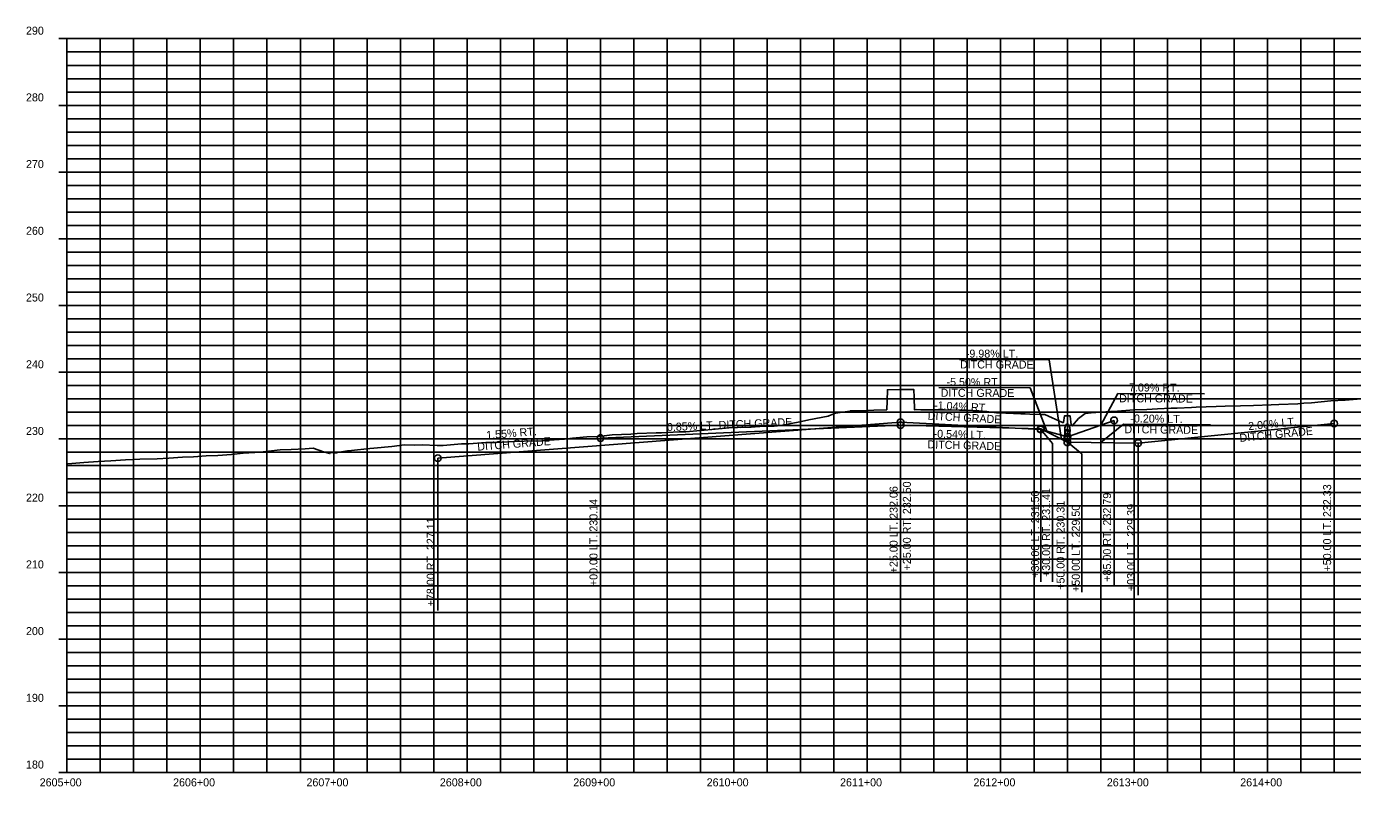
# Model space of a CAD drawing. Extents: x 921603 to 924670, y 1759276 to 1766491.
# Drawn here: x 921610 to 922604, y 1765922 to 1766491 of the extents above; entities that cross this region are included whole.
import ezdxf

# ---------------------------------------------------------------- set-up
doc = ezdxf.new("R2010")
doc.units = 0
for name, color, linetype in [('63', 7, 'Continuous'), ('R_Axis_Annotation', 7, 'Continuous'), ('R_Exist Surface', 7, 'Continuous'), ('R_Grid', 7, 'Continuous'), ('R_Grid Annot', 7, 'Continuous'), ('R_Grid_Minor', 7, 'Continuous'), ('R_Vert Alg', 7, 'Continuous'), ('R_Vert Alg Annot', 7, 'Continuous')]:
    doc.layers.add(name, color=color, linetype=linetype)

msp = doc.modelspace()

# ---------------------------------------------------------------- linework, layer by layer
at = {"layer": 'R_Exist Surface'}
msp.add_lwpolyline([(921639.83, 1766163.54), (921640.46, 1766163.58), (921652.44, 1766164.55), (921663.23, 1766165.41), (921672.8, 1766165.99), (921683.86, 1766166.64), (921694.6, 1766167.01), (921707.48, 1766167.45), (921716.34, 1766167.97), (921726.4, 1766168.63), (921734.64, 1766168.93), (921744.34, 1766169.54), (921752.93, 1766169.86), (921763.3, 1766170.65), (921772.04, 1766171.57), (921784.88, 1766172.47), (921791.06, 1766173.12), (921799.81, 1766174.16), (921807.84, 1766174.43), (921818.48, 1766174.79), (921824.45, 1766175.29), (921832.27, 1766172.66), (921836.95, 1766171.33), (921837.04, 1766171.46), (921837.81, 1766172.06), (921840.02, 1766171.81), (921842, 1766171.78), (921842.41, 1766171.85), (921842.78, 1766172.09), (921844.22, 1766172.46), (921850.22, 1766173.33), (921853.25, 1766173.68), (921866.84, 1766174.99), (921870.05, 1766175.35), (921883.47, 1766176.65), (921892.95, 1766177.74), (921900.25, 1766177.52), (921906.25, 1766177.98), (921917.38, 1766177.39), (921921.94, 1766177.46), (921935.54, 1766178.57), (921941.18, 1766178.61), (921953.79, 1766179.61), (921961.61, 1766179.71), (921974.8, 1766180.33), (921982.51, 1766180.7), (921995.91, 1766180.74), (922001.2, 1766181.24), (922012.78, 1766182.23), (922018.74, 1766182.81), (922029.67, 1766183.75), (922038.61, 1766184.15), (922048.55, 1766185.45), (922062.53, 1766185.79), (922067.36, 1766186.3), (922081.47, 1766186.87), (922085.62, 1766186.95), (922098.93, 1766187.48), (922103.88, 1766187.56), (922117.48, 1766188.9), (922123.23, 1766189.24), (922135.99, 1766190.49), (922142.59, 1766190.84), (922152.91, 1766191.11), (922158.79, 1766191.65), (922170.16, 1766191.92), (922174.93, 1766192.33), (922189.32, 1766195.13), (922192.7, 1766195.82), (922195.92, 1766196.48), (922210.63, 1766199.33), (922211.01, 1766199.6), (922215.97, 1766201.57), (922226.71, 1766203.19), (922227.06, 1766203.22), (922227.24, 1766203.23), (922240.42, 1766203.57), (922244.84, 1766203.81), (922254.29, 1766204.12), (922254.31, 1766204.13), (922254.5, 1766204.14), (922254.7, 1766210.95), (922254.99, 1766219.19), (922264.01, 1766219.38), (922274.66, 1766219.43), (922274.88, 1766213.34), (922275.19, 1766204.21), (922277.01, 1766204.3), (922280.01, 1766204.21), (922290.9, 1766204), (922297.23, 1766204.03), (922309.02, 1766203.78), (922314.46, 1766203.8), (922323.57, 1766203.34), (922329.25, 1766202.74), (922336.63, 1766201.96), (922343.66, 1766201.51), (922354.86, 1766201.08), (922358.11, 1766201), (922361.8, 1766200.91), (922370.52, 1766200.48), (922372.38, 1766200.54), (922372.95, 1766200.55), (922386.25, 1766194.5), (922387.02, 1766194.64), (922387.67, 1766199.57), (922389.92, 1766199.56), (922391.76, 1766199.47), (922392.05, 1766199.39), (922392.76, 1766192.74), (922393.45, 1766192.07), (922398.1, 1766197.47), (922403.12, 1766201.24), (922407.74, 1766201.84), (922422.2, 1766202.74), (922424.5, 1766202.83), (922439.72, 1766204.09), (922449.5, 1766204.24), (922457.48, 1766204.74), (922467.57, 1766205.25), (922472.03, 1766205.36), (922482.89, 1766205.92), (922486.51, 1766206.01), (922501.27, 1766206.62), (922508.12, 1766206.75), (922519.58, 1766206.97), (922529.44, 1766207.31), (922542.67, 1766207.81), (922548.29, 1766208.2), (922562.6, 1766208.69), (922567.13, 1766209.04), (922572.98, 1766209.4), (922587.24, 1766210.75), (922597.98, 1766211.4), (922607.18, 1766212.19)], dxfattribs=at)
at = {"layer": 'R_Grid'}
for p, q in [((921639.83, 1765932.26), (921639.83, 1766482.26)), ((921639.83, 1766482.26), (923139.83, 1766482.26)), ((921639.83, 1766482.26), (923139.83, 1766482.26)), ((921739.83, 1765932.26), (921739.83, 1766482.26)), ((921839.83, 1765932.26), (921839.83, 1766482.26)), ((921939.83, 1765932.26), (921939.83, 1766482.26)), ((922039.83, 1765932.26), (922039.83, 1766482.26)), ((922139.83, 1765932.26), (922139.83, 1766482.26)), ((922239.83, 1765932.26), (922239.83, 1766482.26)), ((922339.83, 1765932.26), (922339.83, 1766482.26)), ((922439.83, 1765932.26), (922439.83, 1766482.26)), ((922539.83, 1765932.26), (922539.83, 1766482.26)), ((921639.83, 1766432.26), (923139.83, 1766432.26)), ((921639.83, 1766382.26), (923139.83, 1766382.26)), ((921639.83, 1766332.26), (923139.83, 1766332.26)), ((921639.83, 1766282.26), (923139.83, 1766282.26)), ((921639.83, 1766232.26), (923139.83, 1766232.26)), ((921639.83, 1766182.26), (923139.83, 1766182.26)), ((921639.83, 1766132.26), (923139.83, 1766132.26)), ((921639.83, 1766082.26), (923139.83, 1766082.26)), ((921639.83, 1766032.26), (923139.83, 1766032.26)), ((921639.83, 1765982.26), (923139.83, 1765982.26)), ((921639.83, 1765932.26), (923139.83, 1765932.26))]:
    msp.add_line(p, q, dxfattribs=at)
at = {"layer": 'R_Grid Annot'}
for p, q in [((921633.83, 1766482.26), (921639.83, 1766482.26)), ((921633.83, 1766482.26), (921639.83, 1766482.26)), ((921639.83, 1766472.26), (921642.83, 1766472.26)), ((921639.83, 1766462.26), (921642.83, 1766462.26)), ((921639.83, 1766452.26), (921642.83, 1766452.26)), ((921639.83, 1766442.26), (921642.83, 1766442.26)), ((921633.83, 1766432.26), (921639.83, 1766432.26)), ((921639.83, 1766422.26), (921642.83, 1766422.26)), ((921639.83, 1766412.26), (921642.83, 1766412.26)), ((921639.83, 1766402.26), (921642.83, 1766402.26)), ((921639.83, 1766392.26), (921642.83, 1766392.26)), ((921633.83, 1766382.26), (921639.83, 1766382.26)), ((921639.83, 1766372.26), (921642.83, 1766372.26)), ((921639.83, 1766362.26), (921642.83, 1766362.26)), ((921639.83, 1766352.26), (921642.83, 1766352.26)), ((921639.83, 1766342.26), (921642.83, 1766342.26)), ((921633.83, 1766332.26), (921639.83, 1766332.26)), ((921639.83, 1766322.26), (921642.83, 1766322.26)), ((921639.83, 1766312.26), (921642.83, 1766312.26)), ((921639.83, 1766302.26), (921642.83, 1766302.26)), ((921639.83, 1766292.26), (921642.83, 1766292.26)), ((921633.83, 1766282.26), (921639.83, 1766282.26)), ((921639.83, 1766272.26), (921642.83, 1766272.26)), ((921639.83, 1766262.26), (921642.83, 1766262.26)), ((921639.83, 1766252.26), (921642.83, 1766252.26)), ((921639.83, 1766242.26), (921642.83, 1766242.26)), ((921633.83, 1766232.26), (921639.83, 1766232.26)), ((921639.83, 1766222.26), (921642.83, 1766222.26)), ((921639.83, 1766212.26), (921642.83, 1766212.26)), ((921639.83, 1766202.26), (921642.83, 1766202.26)), ((921639.83, 1766192.26), (921642.83, 1766192.26)), ((921633.83, 1766182.26), (921639.83, 1766182.26)), ((921639.83, 1766172.26), (921642.83, 1766172.26)), ((921639.83, 1766162.26), (921642.83, 1766162.26)), ((921639.83, 1766152.26), (921642.83, 1766152.26)), ((921639.83, 1766142.26), (921642.83, 1766142.26)), ((921633.83, 1766132.26), (921639.83, 1766132.26)), ((921639.83, 1766122.26), (921642.83, 1766122.26)), ((921639.83, 1766112.26), (921642.83, 1766112.26)), ((921639.83, 1766102.26), (921642.83, 1766102.26)), ((921639.83, 1766092.26), (921642.83, 1766092.26)), ((921633.83, 1766082.26), (921639.83, 1766082.26)), ((921639.83, 1766072.26), (921642.83, 1766072.26)), ((921639.83, 1766062.26), (921642.83, 1766062.26)), ((921639.83, 1766052.26), (921642.83, 1766052.26)), ((921639.83, 1766042.26), (921642.83, 1766042.26)), ((921633.83, 1766032.26), (921639.83, 1766032.26)), ((921639.83, 1766022.26), (921642.83, 1766022.26)), ((921639.83, 1766012.26), (921642.83, 1766012.26)), ((921639.83, 1766002.26), (921642.83, 1766002.26)), ((921639.83, 1765992.26), (921642.83, 1765992.26)), ((921633.83, 1765982.26), (921639.83, 1765982.26)), ((921639.83, 1765972.26), (921642.83, 1765972.26)), ((921639.83, 1765962.26), (921642.83, 1765962.26)), ((921639.83, 1765952.26), (921642.83, 1765952.26)), ((921639.83, 1765942.26), (921642.83, 1765942.26)), ((921633.83, 1765932.26), (921639.83, 1765932.26))]:
    msp.add_line(p, q, dxfattribs=at)
at = {"layer": 'R_Grid_Minor'}
for p, q in [((921664.83, 1765932.26), (921664.83, 1766482.26)), ((921689.83, 1765932.26), (921689.83, 1766482.26)), ((921714.83, 1765932.26), (921714.83, 1766482.26)), ((921764.83, 1765932.26), (921764.83, 1766482.26)), ((921789.83, 1765932.26), (921789.83, 1766482.26)), ((921814.83, 1765932.26), (921814.83, 1766482.26)), ((921864.83, 1765932.26), (921864.83, 1766482.26)), ((921889.83, 1765932.26), (921889.83, 1766482.26)), ((921914.83, 1765932.26), (921914.83, 1766482.26)), ((921964.83, 1765932.26), (921964.83, 1766482.26)), ((921989.83, 1765932.26), (921989.83, 1766482.26)), ((922014.83, 1765932.26), (922014.83, 1766482.26)), ((922064.83, 1765932.26), (922064.83, 1766482.26)), ((922089.83, 1765932.26), (922089.83, 1766482.26)), ((922114.83, 1765932.26), (922114.83, 1766482.26)), ((922164.83, 1765932.26), (922164.83, 1766482.26)), ((922189.83, 1765932.26), (922189.83, 1766482.26)), ((922214.83, 1765932.26), (922214.83, 1766482.26)), ((922264.83, 1765932.26), (922264.83, 1766482.26)), ((922289.83, 1765932.26), (922289.83, 1766482.26)), ((922314.83, 1765932.26), (922314.83, 1766482.26)), ((922364.83, 1765932.26), (922364.83, 1766482.26)), ((922389.83, 1765932.26), (922389.83, 1766482.26)), ((922414.83, 1765932.26), (922414.83, 1766482.26)), ((922464.83, 1765932.26), (922464.83, 1766482.26)), ((922489.83, 1765932.26), (922489.83, 1766482.26)), ((922514.83, 1765932.26), (922514.83, 1766482.26)), ((922564.83, 1765932.26), (922564.83, 1766482.26)), ((922589.83, 1765932.26), (922589.83, 1766482.26)), ((921639.83, 1766472.26), (923139.83, 1766472.26)), ((921639.83, 1766462.26), (923139.83, 1766462.26)), ((921639.83, 1766452.26), (923139.83, 1766452.26)), ((921639.83, 1766442.26), (923139.83, 1766442.26)), ((921639.83, 1766422.26), (923139.83, 1766422.26)), ((921639.83, 1766412.26), (923139.83, 1766412.26)), ((921639.83, 1766402.26), (923139.83, 1766402.26)), ((921639.83, 1766392.26), (923139.83, 1766392.26)), ((921639.83, 1766372.26), (923139.83, 1766372.26)), ((921639.83, 1766362.26), (923139.83, 1766362.26)), ((921639.83, 1766352.26), (923139.83, 1766352.26)), ((921639.83, 1766342.26), (923139.83, 1766342.26)), ((921639.83, 1766322.26), (923139.83, 1766322.26)), ((921639.83, 1766312.26), (923139.83, 1766312.26)), ((921639.83, 1766302.26), (923139.83, 1766302.26)), ((921639.83, 1766292.26), (923139.83, 1766292.26)), ((921639.83, 1766272.26), (923139.83, 1766272.26)), ((921639.83, 1766262.26), (923139.83, 1766262.26)), ((921639.83, 1766252.26), (923139.83, 1766252.26)), ((921639.83, 1766242.26), (923139.83, 1766242.26)), ((921639.83, 1766222.26), (923139.83, 1766222.26)), ((921639.83, 1766212.26), (923139.83, 1766212.26)), ((921639.83, 1766202.26), (923139.83, 1766202.26)), ((921639.83, 1766192.26), (923139.83, 1766192.26)), ((921639.83, 1766172.26), (923139.83, 1766172.26)), ((921639.83, 1766162.26), (923139.83, 1766162.26)), ((921639.83, 1766152.26), (923139.83, 1766152.26)), ((921639.83, 1766142.26), (923139.83, 1766142.26)), ((921639.83, 1766122.26), (923139.83, 1766122.26)), ((921639.83, 1766112.26), (923139.83, 1766112.26)), ((921639.83, 1766102.26), (923139.83, 1766102.26)), ((921639.83, 1766092.26), (923139.83, 1766092.26)), ((921639.83, 1766072.26), (923139.83, 1766072.26)), ((921639.83, 1766062.26), (923139.83, 1766062.26)), ((921639.83, 1766052.26), (923139.83, 1766052.26)), ((921639.83, 1766042.26), (923139.83, 1766042.26)), ((921639.83, 1766022.26), (923139.83, 1766022.26)), ((921639.83, 1766012.26), (923139.83, 1766012.26)), ((921639.83, 1766002.26), (923139.83, 1766002.26)), ((921639.83, 1765992.26), (923139.83, 1765992.26)), ((921639.83, 1765972.26), (923139.83, 1765972.26)), ((921639.83, 1765962.26), (923139.83, 1765962.26)), ((921639.83, 1765952.26), (923139.83, 1765952.26)), ((921639.83, 1765942.26), (923139.83, 1765942.26))]:
    msp.add_line(p, q, dxfattribs=at)
at = {"layer": 'R_Vert Alg'}
for p, q in [((921917.83, 1766167.81), (922264.83, 1766194.76)), ((922039.83, 1766182.96), (922264.83, 1766192.56)), ((922264.83, 1766194.76), (922369.83, 1766189.31)), ((922264.83, 1766192.56), (922369.83, 1766189.73)), ((922389.83, 1766183.81), (922424.83, 1766196.21)), ((922442.83, 1766179.23), (922589.83, 1766193.91)), ((922369.83, 1766189.73), (922389.83, 1766179.76)), ((922369.83, 1766189.31), (922389.83, 1766183.81)), ((922389.83, 1766179.76), (922442.83, 1766179.23))]:
    msp.add_line(p, q, dxfattribs=at)
at = {"layer": 'R_Vert Alg Annot'}
for p, q in [((922376.19, 1766241.64), (922309.08, 1766241.75)), ((922376.19, 1766241.64), (922385.51, 1766181.92)), ((922361.9, 1766220.48), (922293.5, 1766220.77)), ((922361.9, 1766220.48), (922374.56, 1766188.01)), ((922427.57, 1766216.37), (922414.83, 1766192.67)), ((922427.57, 1766216.37), (922492.57, 1766216.1)), ((922264.83, 1766194.76), (922264.83, 1766164.76)), ((922264.83, 1766192.56), (922264.83, 1766162.56)), ((922432.02, 1766193.42), (922414.83, 1766179.51)), ((922424.83, 1766196.21), (922424.83, 1766166.21)), ((922432.02, 1766193.42), (922497.03, 1766192.77)), ((922589.83, 1766193.91), (922589.83, 1766163.91)), ((922039.83, 1766182.96), (922039.83, 1766152.96)), ((922369.83, 1766189.73), (922369.83, 1766159.73)), ((922369.83, 1766189.31), (922378.59, 1766178.96)), ((922369.83, 1766189.31), (922369.83, 1766159.31)), ((922389.83, 1766183.81), (922389.83, 1766153.81)), ((922378.59, 1766178.96), (922378.59, 1766075.31)), ((922389.83, 1766179.76), (922400.78, 1766171.17)), ((922389.83, 1766179.76), (922389.83, 1766149.76)), ((922400.78, 1766171.17), (922400.78, 1766067.4)), ((922442.83, 1766179.23), (922442.83, 1766149.23)), ((921917.83, 1766167.81), (921917.83, 1766137.81)), ((922264.83, 1766164.76), (922264.83, 1766080.76)), ((922264.83, 1766162.56), (922264.83, 1766078.56)), ((922424.83, 1766166.21), (922424.83, 1766072.25)), ((922589.83, 1766163.91), (922589.83, 1766079.91)), ((922039.83, 1766152.96), (922039.83, 1766068.96)), ((922369.83, 1766159.73), (922369.83, 1766075.73)), ((922369.83, 1766159.31), (922369.83, 1766075.31)), ((922389.83, 1766153.81), (922389.83, 1766069.81)), ((922389.83, 1766149.76), (922389.83, 1766065.76)), ((922442.83, 1766149.23), (922442.83, 1766065.23)), ((921917.83, 1766137.81), (921917.83, 1766053.81))]:
    msp.add_line(p, q, dxfattribs=at)
for centre in [(922264.83, 1766194.76), (922264.83, 1766192.56), (922369.83, 1766189.73), (922369.83, 1766189.31), (922424.83, 1766196.21), (922589.83, 1766193.91), (922039.83, 1766182.96), (922389.83, 1766183.81), (922389.83, 1766179.76), (922442.83, 1766179.23), (921917.83, 1766167.81)]:
    msp.add_circle(centre, 2.5, dxfattribs=at)
for centre in [(922389.83, 1766188.7), (922389.83, 1766184.65)]:
    msp.add_ellipse(centre, major_axis=(0, 4.89), ratio=0.408862, dxfattribs=at)

# ---------------------------------------------------------------- texts
at = {"layer": '63'}
msp.add_text('-', height=0.0001, dxfattribs=at).set_placement((921639.83, 1765932.26))
at = {"layer": 'R_Axis_Annotation'}
for s, p in [('290', (921609.16, 1766485.26)), ('290', (921609.16, 1766485.26)), ('280', (921609.16, 1766435.26)), ('270', (921609.16, 1766385.26)), ('260', (921609.16, 1766335.26)), ('250', (921609.16, 1766285.26)), ('240', (921609.16, 1766235.26)), ('230', (921609.16, 1766185.26)), ('220', (921609.16, 1766135.26)), ('210', (921609.16, 1766085.26)), ('200', (921609.16, 1766035.26)), ('190', (921609.16, 1765985.26)), ('180', (921609.16, 1765935.26)), ('2605+00', (921619.42, 1765921.91)), ('2606+00', (921719.42, 1765921.91)), ('2607+00', (921819.42, 1765921.91)), ('2608+00', (921919.42, 1765921.91)), ('2609+00', (922019.42, 1765921.91)), ('2610+00', (922119.42, 1765921.91)), ('2611+00', (922219.42, 1765921.91)), ('2612+00', (922319.42, 1765921.91)), ('2613+00', (922419.42, 1765921.91)), ('2614+00', (922519.42, 1765921.91))]:
    msp.add_text(s, height=6, dxfattribs=at).set_placement(p)
at = {"layer": 'R_Vert Alg Annot'}
for s, rotation, p in [('DITCH GRADE', 359.90265, (922309.33, 1766235.12)), ('-9.98% LT.', 359.90265, (922313.72, 1766243.24)), ('DITCH GRADE', 359.76945, (922294.83, 1766213.89)), ('-5.50% RT.', 359.76945, (922299.24, 1766222)), ('7.09% RT.', 359.76885, (922436.02, 1766217.86)), ('-1.04% RT.', 357.02874, (922289.82, 1766204.6)), ('DITCH GRADE', 359.76885, (922428.61, 1766209.76)), ('DITCH GRADE', 357.02874, (922285.02, 1766196.72)), ('-0.20% LT.', 359.42706, (922437.03, 1766194.66)), ('1.55% RT.', 4.441, (921954.43, 1766182.11)), ('0.85% LT. DITCH GRADE', 2.44314, (922089.75, 1766188.09)), ('DITCH GRADE', 359.42706, (922432.57, 1766186.58)), ('DITCH GRADE', 5.70287, (922519.19, 1766179.99)), ('2.00% LT.', 5.70287, (922525.73, 1766188.81)), ('DITCH GRADE', 4.441, (921947.7, 1766173.44)), ('DITCH GRADE', 358.45884, (922284.92, 1766175.26)), ('-0.54% LT.', 358.45884, (922289.51, 1766183.26)), ('+25.00 RT. 232.50', 90, (922272.53, 1766083.76)), ('+25.00 LT. 232.06', 90, (922262.58, 1766081.56)), ('+30.00 LT. 231.50', 90, (922368.67, 1766078.29)), ('+30.00 RT. 231.41', 90, (922376.91, 1766078.82)), ('+85.00 RT. 232.79', 90, (922422.58, 1766075.25)), ('+50.00 LT. 232.33', 90, (922587.58, 1766082.91)), ('+00.00 LT. 230.14', 90, (922037.58, 1766071.96)), ('+50.00 RT. 230.31', 90, (922387.73, 1766069.24)), ('+50.00 LT. 229.50', 90, (922399.16, 1766067.62)), ('+03.00 LT. 229.39', 90, (922440.58, 1766068.23)), ('+78.00 RT. 227.11', 90, (921915.58, 1766056.81))]:
    msp.add_text(s, height=6, rotation=rotation, dxfattribs=at).set_placement(p)

doc.saveas('drawing.dxf')
